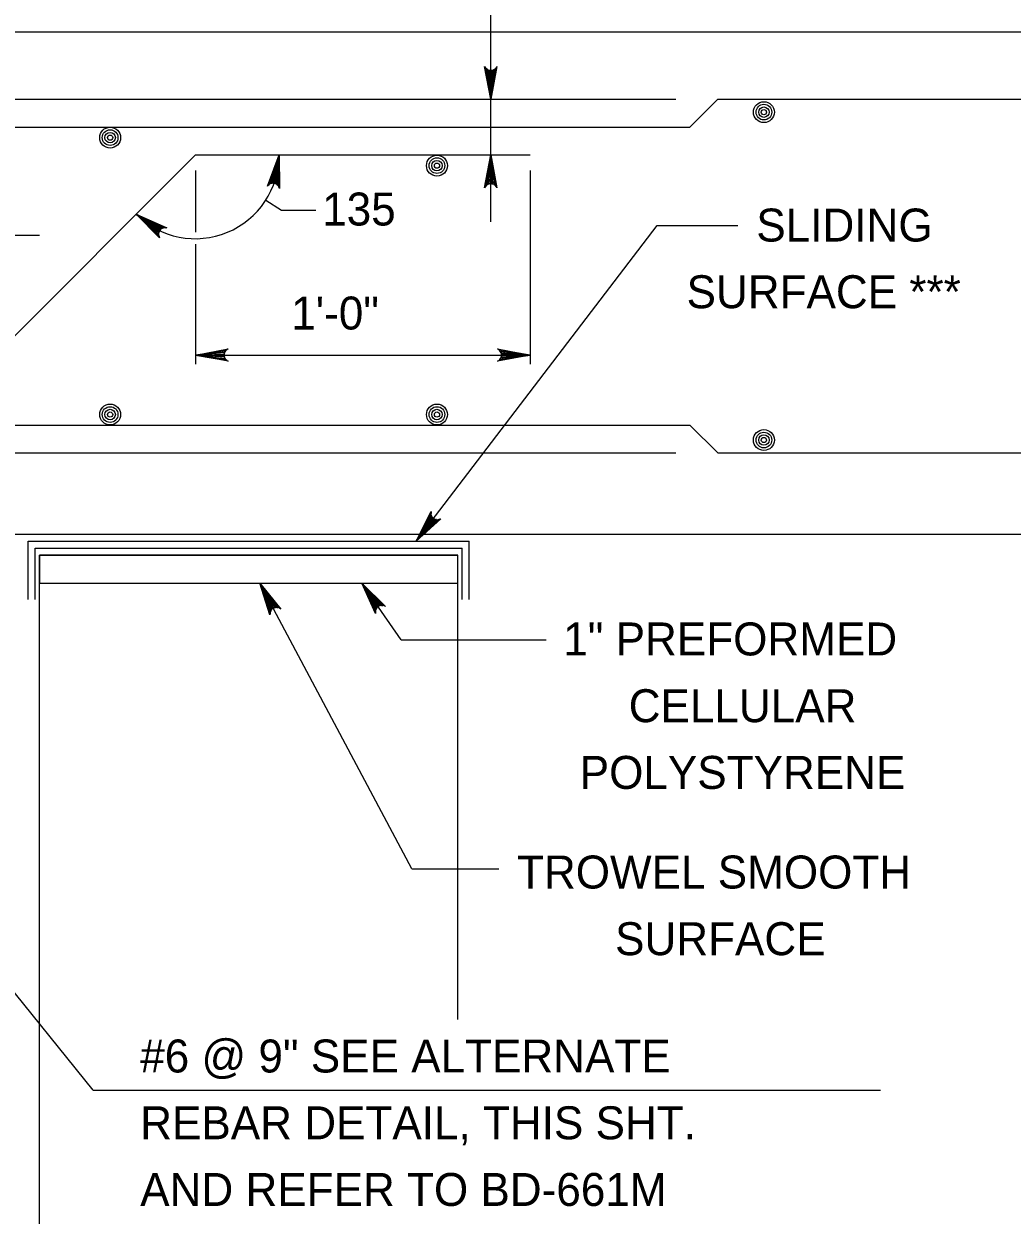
# Model space of a CAD drawing. Extents: x 636530 to 644067, y 294168 to 299122.
# Drawn here: x 638393.2 to 638483.2, y 295758.6 to 295867 of the extents above; entities that cross this region are included whole.
import ezdxf

# ---------------------------------------------------------------- set-up
doc = ezdxf.new("R2010")
doc.units = 0
doc.layers.add('1', color=7, linetype='Continuous')

msp = doc.modelspace()

# ---------------------------------------------------------------- linework, layer by layer
at = {"layer": '1'}
for p, q in [((638435.69, 295849.02), (638435.69, 295875.83)), ((638359.2, 295866.3), (638507.86, 295866.3)), ((638368.73, 295860.18), (638452.55, 295860.18)), ((638453.82, 295857.64), (638456.36, 295860.18)), ((638456.36, 295860.18), (638507.86, 295860.18)), ((638369.95, 295857.64), (638453.82, 295857.64)), ((638343.74, 295790.04), (638408.79, 295855.1)), ((638408.79, 295855.1), (638439.27, 295855.1)), ((638408.79, 295853.69), (638408.79, 295848.07)), ((638439.27, 295853.69), (638439.27, 295836.05)), ((638415.21, 295850.99), (638416.62, 295850.09)), ((638416.62, 295850.09), (638419.77, 295850.09)), ((638428.89, 295819.94), (638450.85, 295848.67)), ((638450.85, 295848.67), (638458.19, 295848.67)), ((638368.49, 295847.79), (638394.6, 295847.79)), ((638408.79, 295846.97), (638408.79, 295836.05)), ((638408.79, 295836.88), (638439.27, 295836.88)), ((638369.95, 295830.51), (638453.82, 295830.51)), ((638453.82, 295830.51), (638456.36, 295827.97)), ((638368.73, 295827.97), (638452.55, 295827.97)), ((638456.36, 295827.97), (638507.86, 295827.97)), ((638358.52, 295820.58), (638507.86, 295820.58)), ((638393.56, 295819.94), (638433.72, 295819.94)), ((638393.56, 295814.63), (638393.56, 295819.94)), ((638394.19, 295819.31), (638433.09, 295819.31)), ((638394.19, 295814.63), (638394.19, 295819.31)), ((638433.09, 295814.63), (638433.09, 295819.31)), ((638433.72, 295814.63), (638433.72, 295819.94)), ((638394.59, 295709.24), (638394.59, 295818.67)), ((638394.59, 295818.67), (638432.69, 295818.67)), ((638432.69, 295776.39), (638432.69, 295818.67)), ((638394.59, 295816.13), (638432.69, 295816.13)), ((638428.49, 295790.12), (638414.67, 295816.13)), ((638427.54, 295810.95), (638423.95, 295816.13)), ((638427.54, 295810.95), (638440.73, 295810.95)), ((638399.49, 295769.96), (638372.55, 295803.31)), ((638428.49, 295790.12), (638436.42, 295790.12)), ((638399.49, 295769.96), (638471.18, 295769.96))]:
    msp.add_line(p, q, dxfattribs=at)
for points in [[(638435.69, 295860.18), (638435.13, 295863.16), (638435.21, 295863.04), (638435.29, 295862.93), (638435.39, 295862.87), (638435.49, 295862.81), (638435.59, 295862.79), (638435.69, 295862.78), (638435.79, 295862.79), (638435.89, 295862.81), (638435.99, 295862.87), (638436.09, 295862.93), (638436.17, 295863.04), (638436.25, 295863.16), (638435.69, 295860.18), (638436.17, 295863.04), (638436.09, 295862.93), (638435.69, 295860.18), (638435.99, 295862.87), (638435.89, 295862.81), (638435.69, 295860.18), (638435.79, 295862.79), (638435.69, 295862.78), (638435.69, 295860.18), (638435.59, 295862.79), (638435.49, 295862.81), (638435.69, 295860.18), (638435.39, 295862.87), (638435.29, 295862.93), (638435.69, 295860.18), (638435.21, 295863.04)], [(638416.41, 295855.1), (638416.45, 295852.06), (638416.39, 295852.19), (638416.33, 295852.32), (638416.24, 295852.39), (638416.15, 295852.47), (638416.06, 295852.5), (638415.96, 295852.54), (638415.86, 295852.54), (638415.76, 295852.54), (638415.65, 295852.5), (638415.54, 295852.46), (638415.44, 295852.36), (638415.35, 295852.26), (638416.41, 295855.1), (638415.44, 295852.36), (638415.54, 295852.46), (638416.41, 295855.1), (638415.65, 295852.5), (638415.76, 295852.54), (638416.41, 295855.1), (638415.86, 295852.54), (638415.96, 295852.54), (638416.41, 295855.1), (638416.06, 295852.5), (638416.15, 295852.47), (638416.41, 295855.1), (638416.24, 295852.39), (638416.33, 295852.32), (638416.41, 295855.1), (638416.39, 295852.19)], [(638435.69, 295855.1), (638436.25, 295852.12), (638436.17, 295852.23), (638436.09, 295852.35), (638435.99, 295852.41), (638435.89, 295852.46), (638435.79, 295852.48), (638435.69, 295852.5), (638435.59, 295852.48), (638435.49, 295852.46), (638435.39, 295852.41), (638435.29, 295852.35), (638435.21, 295852.23), (638435.13, 295852.12), (638435.69, 295855.1), (638435.21, 295852.23), (638435.29, 295852.35), (638435.69, 295855.1), (638435.39, 295852.41), (638435.49, 295852.46), (638435.69, 295855.1), (638435.59, 295852.48), (638435.69, 295852.5), (638435.69, 295855.1), (638435.79, 295852.48), (638435.89, 295852.46), (638435.69, 295855.1), (638435.99, 295852.41), (638436.09, 295852.35), (638435.69, 295855.1), (638436.17, 295852.23)], [(638403.41, 295849.71), (638406.18, 295848.48), (638406.04, 295848.48), (638405.9, 295848.48), (638405.79, 295848.43), (638405.69, 295848.38), (638405.62, 295848.31), (638405.55, 295848.23), (638405.5, 295848.14), (638405.46, 295848.05), (638405.45, 295847.93), (638405.44, 295847.82), (638405.49, 295847.69), (638405.54, 295847.56), (638403.41, 295849.71), (638405.49, 295847.69), (638405.44, 295847.82), (638403.41, 295849.71), (638405.45, 295847.93), (638405.46, 295848.05), (638403.41, 295849.71), (638405.5, 295848.14), (638405.55, 295848.23), (638403.41, 295849.71), (638405.62, 295848.31), (638405.69, 295848.38), (638403.41, 295849.71), (638405.79, 295848.43), (638405.9, 295848.48), (638403.41, 295849.71), (638406.04, 295848.48)], [(638408.79, 295836.88), (638411.78, 295837.44), (638411.66, 295837.36), (638411.55, 295837.28), (638411.49, 295837.18), (638411.43, 295837.08), (638411.41, 295836.98), (638411.39, 295836.88), (638411.41, 295836.78), (638411.43, 295836.68), (638411.49, 295836.58), (638411.55, 295836.48), (638411.66, 295836.4), (638411.78, 295836.32), (638408.79, 295836.88), (638411.66, 295836.4), (638411.55, 295836.48), (638408.79, 295836.88), (638411.49, 295836.58), (638411.43, 295836.68), (638408.79, 295836.88), (638411.41, 295836.78), (638411.39, 295836.88), (638408.79, 295836.88), (638411.41, 295836.98), (638411.43, 295837.08), (638408.79, 295836.88), (638411.49, 295837.18), (638411.55, 295837.28), (638408.79, 295836.88), (638411.66, 295837.36)], [(638439.27, 295836.88), (638436.29, 295836.32), (638436.41, 295836.4), (638436.52, 295836.48), (638436.58, 295836.58), (638436.64, 295836.68), (638436.66, 295836.78), (638436.67, 295836.88), (638436.66, 295836.98), (638436.64, 295837.08), (638436.58, 295837.18), (638436.52, 295837.28), (638436.41, 295837.36), (638436.29, 295837.44), (638439.27, 295836.88), (638436.41, 295837.36), (638436.52, 295837.28), (638439.27, 295836.88), (638436.58, 295837.18), (638436.64, 295837.08), (638439.27, 295836.88), (638436.66, 295836.98), (638436.67, 295836.88), (638439.27, 295836.88), (638436.66, 295836.78), (638436.64, 295836.68), (638439.27, 295836.88), (638436.58, 295836.58), (638436.52, 295836.48), (638439.27, 295836.88), (638436.41, 295836.4)], [(638428.89, 295819.94), (638430.26, 295822.65), (638430.25, 295822.51), (638430.24, 295822.37), (638430.29, 295822.26), (638430.33, 295822.15), (638430.4, 295822.08), (638430.47, 295822.01), (638430.56, 295821.96), (638430.65, 295821.91), (638430.76, 295821.9), (638430.88, 295821.88), (638431.01, 295821.93), (638431.14, 295821.97), (638428.89, 295819.94), (638431.01, 295821.93), (638430.88, 295821.88), (638428.89, 295819.94), (638430.76, 295821.9), (638430.65, 295821.91), (638428.89, 295819.94), (638430.56, 295821.96), (638430.47, 295822.01), (638428.89, 295819.94), (638430.4, 295822.08), (638430.33, 295822.15), (638428.89, 295819.94), (638430.29, 295822.26), (638430.24, 295822.37), (638428.89, 295819.94), (638430.25, 295822.51)], [(638414.67, 295816.13), (638416.56, 295813.76), (638416.44, 295813.83), (638416.31, 295813.89), (638416.2, 295813.9), (638416.08, 295813.9), (638415.99, 295813.87), (638415.89, 295813.84), (638415.81, 295813.78), (638415.73, 295813.71), (638415.67, 295813.61), (638415.61, 295813.51), (638415.59, 295813.38), (638415.57, 295813.24), (638414.67, 295816.13), (638415.59, 295813.38), (638415.61, 295813.51), (638414.67, 295816.13), (638415.67, 295813.61), (638415.73, 295813.71), (638414.67, 295816.13), (638415.81, 295813.78), (638415.89, 295813.84), (638414.67, 295816.13), (638415.99, 295813.87), (638416.08, 295813.9), (638414.67, 295816.13), (638416.2, 295813.9), (638416.31, 295813.89), (638414.67, 295816.13), (638416.44, 295813.83)], [(638423.95, 295816.13), (638426.11, 295814), (638425.98, 295814.05), (638425.85, 295814.1), (638425.73, 295814.09), (638425.62, 295814.08), (638425.53, 295814.04), (638425.43, 295814), (638425.36, 295813.93), (638425.29, 295813.85), (638425.24, 295813.75), (638425.19, 295813.64), (638425.19, 295813.5), (638425.19, 295813.36), (638423.95, 295816.13), (638425.19, 295813.5), (638425.19, 295813.64), (638423.95, 295816.13), (638425.24, 295813.75), (638425.29, 295813.85), (638423.95, 295816.13), (638425.36, 295813.93), (638425.43, 295814), (638423.95, 295816.13), (638425.53, 295814.04), (638425.62, 295814.08), (638423.95, 295816.13), (638425.73, 295814.09), (638425.85, 295814.1), (638423.95, 295816.13), (638425.98, 295814.05)]]:
    msp.add_lwpolyline(points, dxfattribs=at)
msp.add_lwpolyline([(638394.59, 295816.13), (638432.69, 295816.13), (638432.69, 295818.67), (638394.59, 295818.67)], close=True, dxfattribs=at)
for centre, radius in [((638460.56, 295859), 0.952), ((638460.56, 295859), 0.714), ((638460.56, 295859), 0.476), ((638460.56, 295859), 0.238), ((638401.03, 295856.68), 0.952), ((638401.03, 295856.68), 0.714), ((638401.03, 295856.68), 0.476), ((638401.03, 295856.68), 0.238), ((638430.79, 295854.13), 0.952), ((638430.79, 295854.13), 0.714), ((638430.79, 295854.13), 0.476), ((638430.79, 295854.13), 0.238), ((638401.03, 295831.47), 0.952), ((638430.79, 295831.47), 0.952), ((638401.03, 295831.47), 0.714), ((638401.03, 295831.47), 0.476), ((638401.03, 295831.47), 0.238), ((638430.79, 295831.47), 0.714), ((638430.79, 295831.47), 0.476), ((638430.79, 295831.47), 0.238), ((638460.56, 295829.15), 0.952), ((638460.56, 295829.15), 0.714), ((638460.56, 295829.15), 0.476), ((638460.56, 295829.15), 0.238)]:
    msp.add_circle(centre, radius, dxfattribs=at)
msp.add_arc((638408.79, 295855.1), 7.62, 225, 0, dxfattribs=at)

# ---------------------------------------------------------------- texts
for s, p in [('135', (638420.34, 295848.68)), ('SLIDING', (638459.87, 295847.22)), ('SURFACE ***', (638453.52, 295841.15)), ('1\'-0"', (638417.52, 295839.21)), ('1" PREFORMED', (638442.29, 295809.54)), ('CELLULAR', (638448.25, 295803.46)), ('POLYSTYRENE', (638443.79, 295797.39)), ('TROWEL SMOOTH', (638438.08, 295788.32)), ('SURFACE', (638447.01, 295782.25)), ('#6 @ 9" SEE ALTERNATE', (638403.77, 295771.57)), ('REBAR DETAIL, THIS SHT.', (638403.77, 295765.49)), ('AND REFER TO BD-661M', (638403.77, 295759.42))]:
    msp.add_text(s, height=3, rotation=360, dxfattribs=at).set_placement(p)

doc.saveas('drawing.dxf')
